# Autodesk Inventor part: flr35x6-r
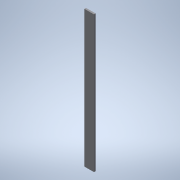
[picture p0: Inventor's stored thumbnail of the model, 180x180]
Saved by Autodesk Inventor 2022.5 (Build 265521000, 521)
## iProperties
Created: 2016-12
Part Number: flr35x6-r
Material: 一般
Document SubType Name: Modeling
Designer: imaocorp
Density: 1 g/cm^3
Appearance: 既定
Author: imaocorp
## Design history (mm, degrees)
node "flr35x6-r.x_t1"
node "flr35x6-r"
node "Base1"
